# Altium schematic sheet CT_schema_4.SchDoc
size 578 x 363 mm
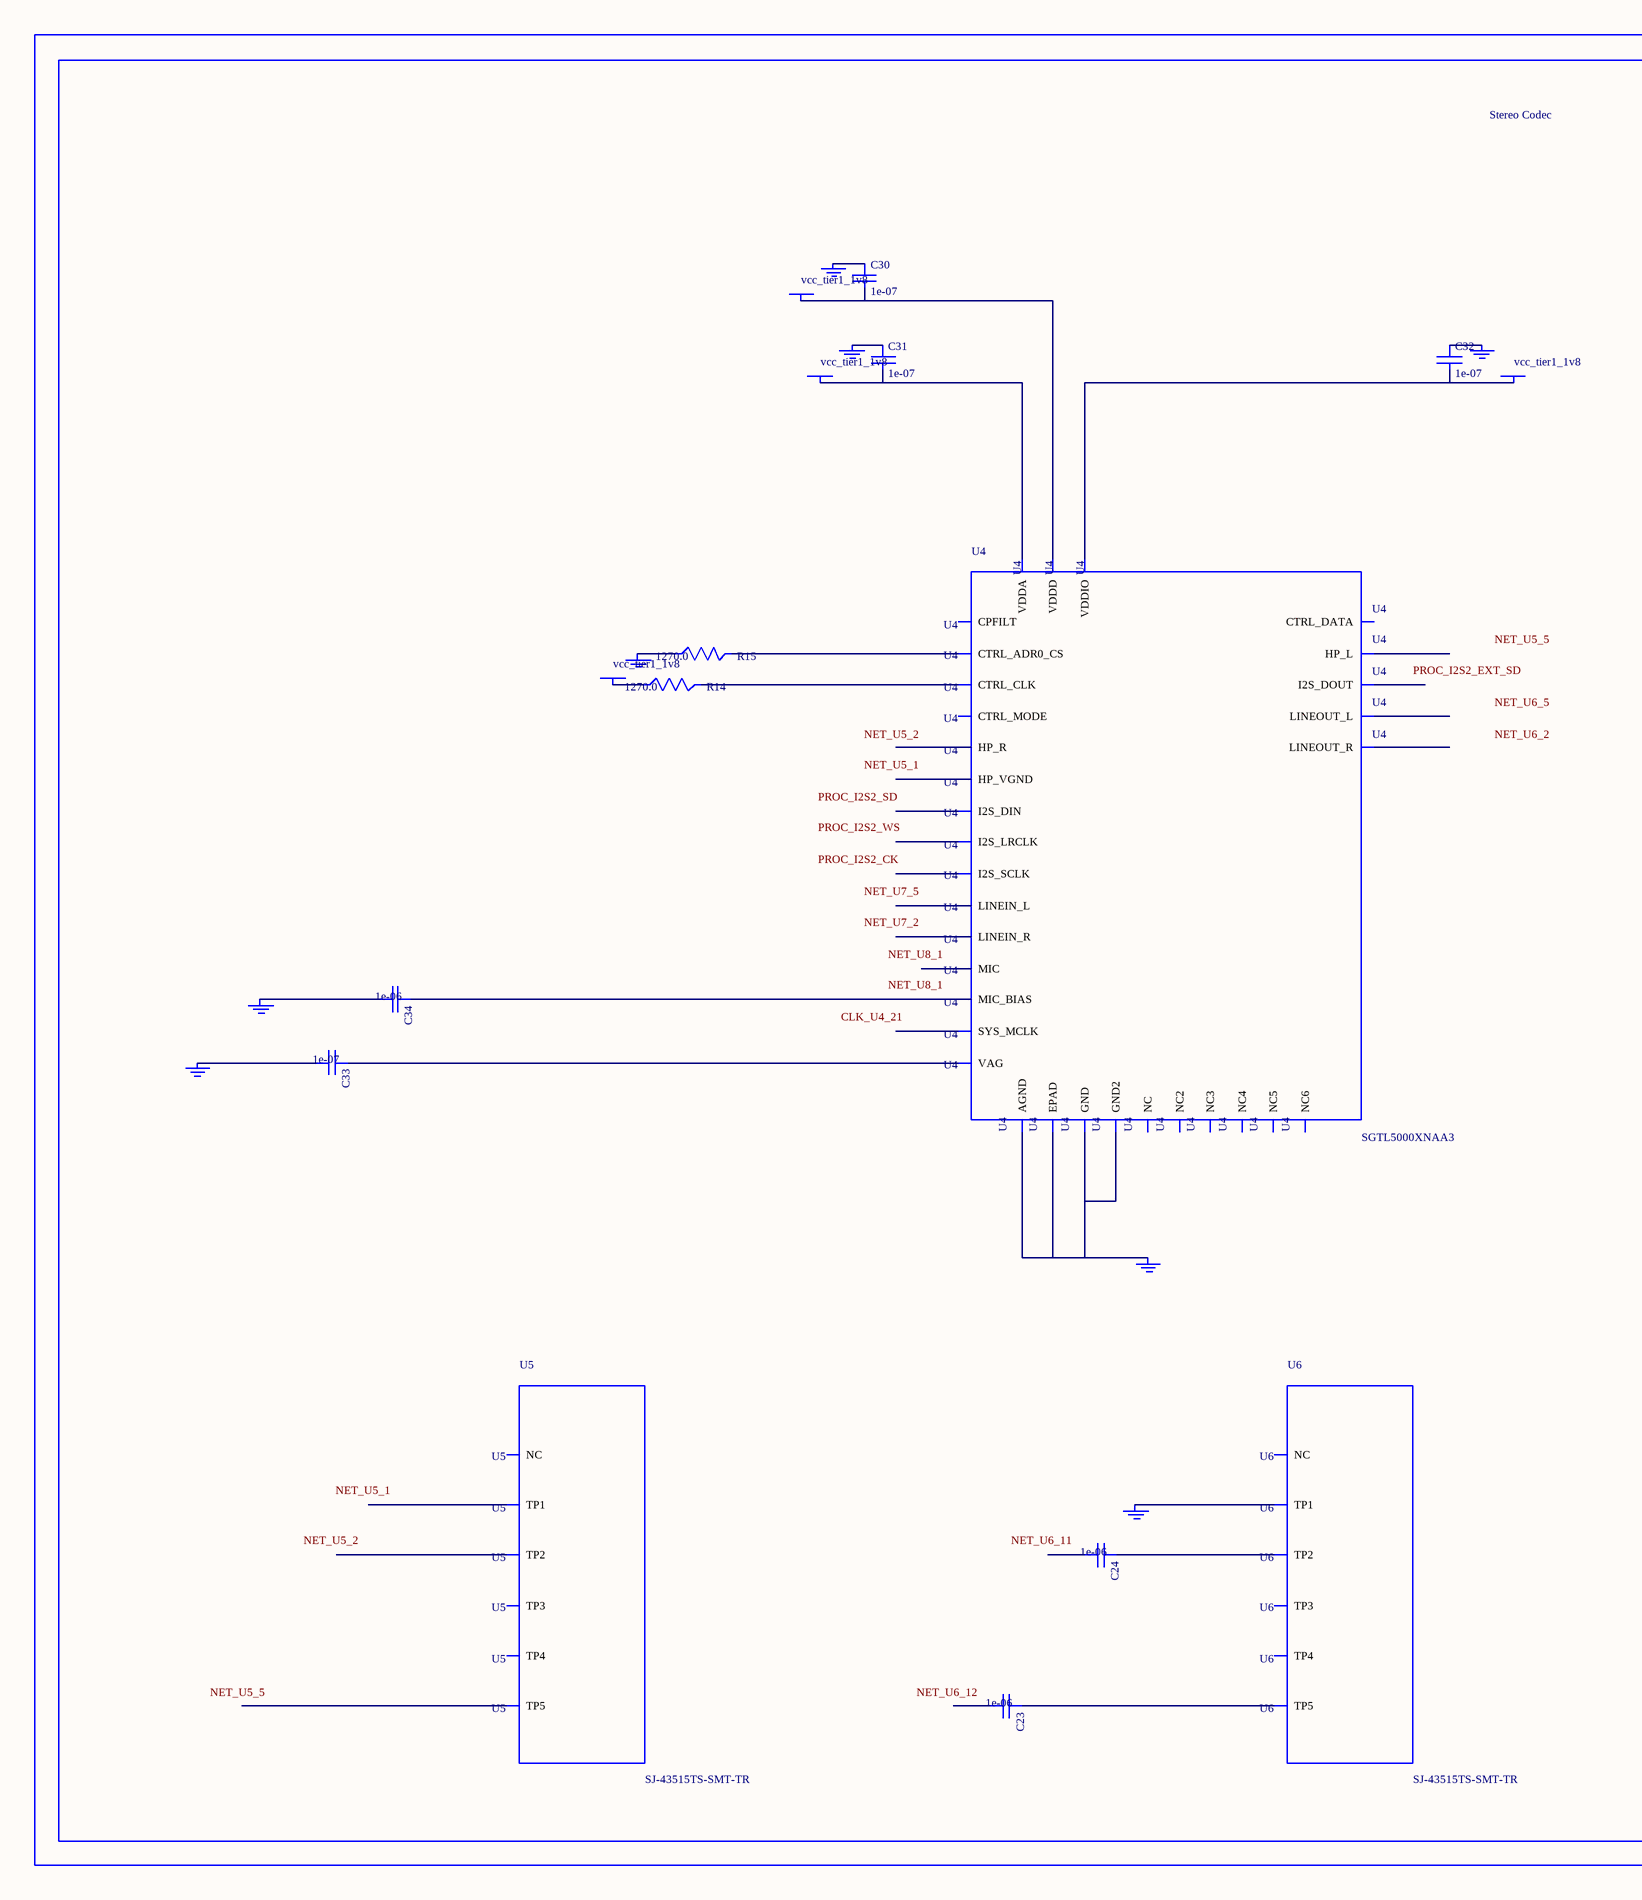
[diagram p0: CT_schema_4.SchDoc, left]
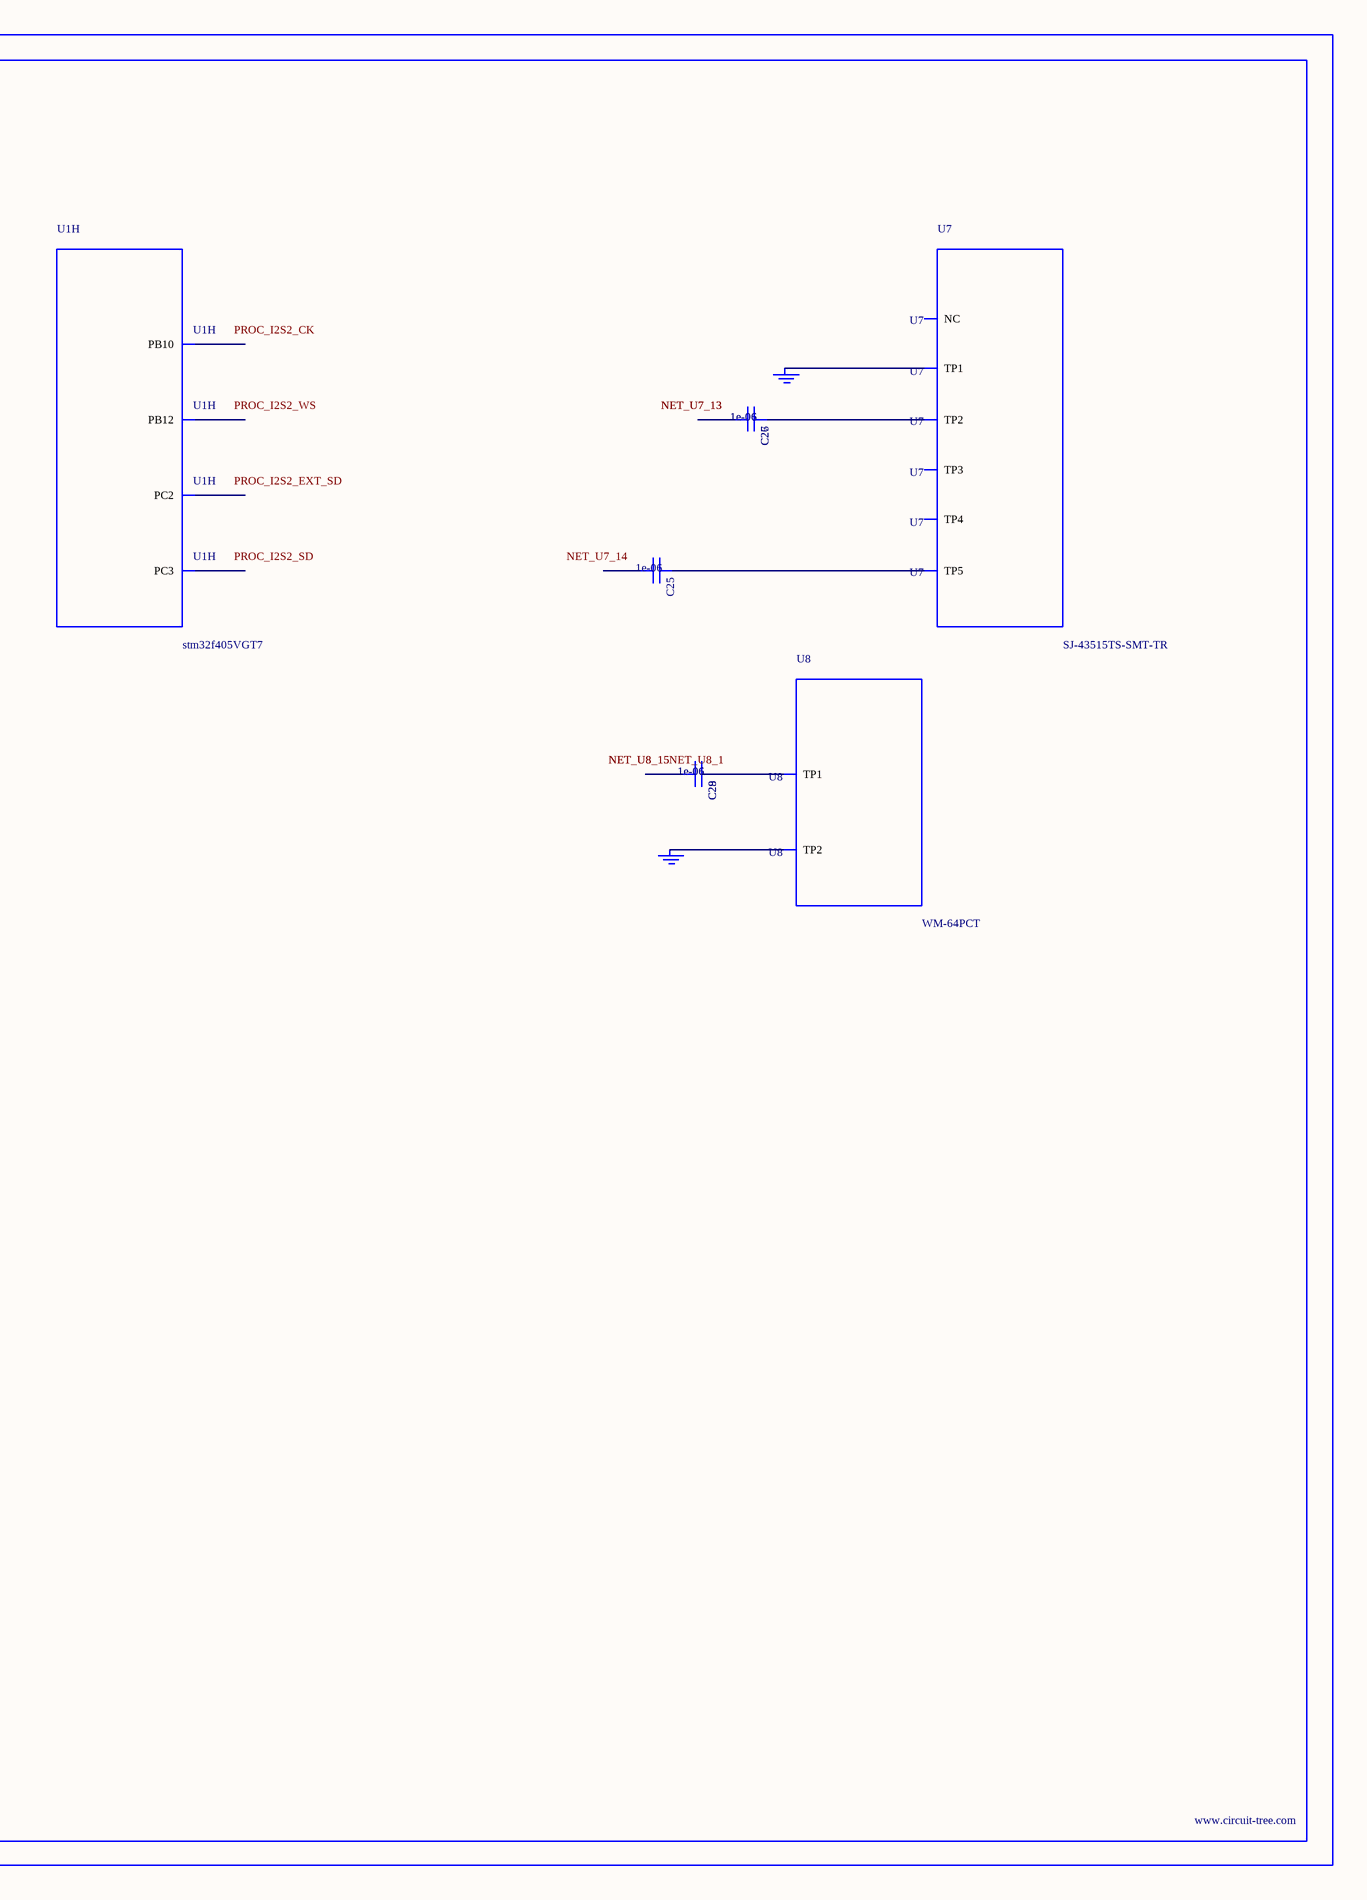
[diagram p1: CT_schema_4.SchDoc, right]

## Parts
BORDER3  (no value)
C23  1e-06  [C0603]
C24  1e-06  [C0603]
C25  1e-06  [C0603]
C26  1e-06  [C0603]
C27  1e-06  [C0603]
C28  1e-06  [C0603]
C29  1e-06  [C0603]
C30  1e-07  [C0402]
C31  1e-07  [C0402]
C32  1e-07  [C0402]
C33  1e-07  [C0402]
C34  1e-06  [C0603]
GND_INSTANCE_3_0  (no value)
GND_INSTANCE_3_1  (no value)
GND_INSTANCE_3_2  (no value)
GND_INSTANCE_3_3  (no value)
GND_INSTANCE_3_4  (no value)
GND_INSTANCE_3_5  (no value)
GND_INSTANCE_3_6  (no value)
GND_INSTANCE_3_7  (no value)
GND_INSTANCE_3_8  (no value)
GND_INSTANCE_3_9  (no value)
GND_INSTANCE_3_10  (no value)
POWER_INSTANCE_3_0  vcc_tier1_1v8
POWER_INSTANCE_3_1  vcc_tier1_1v8
POWER_INSTANCE_3_2  vcc_tier1_1v8
POWER_INSTANCE_3_3  vcc_tier1_1v8
R14  1270.0  [R0603]
R15  1270.0  [R0603]
U1  stm32f405VGT7  [LQFP100]  (part H of 10)
U4  SGTL5000XNAA3  [QFN-32]
U5  SJ-43515TS-SMT-TR  [SJ-43515TS-SMT-TR]
U6  SJ-43515TS-SMT-TR  [SJ-43515TS-SMT-TR]
U7  SJ-43515TS-SMT-TR  [SJ-43515TS-SMT-TR]
U8  WM-64PCT  [WM-64PC]

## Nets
NetC23_1: C23.1 U6.5(TP5)
NetC24_1: C24.1 U6.2(TP2)
NetC25_1: C25.1 U7.5(TP5)
NetC26_1: C26.1 C27.1 U7.2(TP2)
NetC26_2: C26.2 C27.2
NetC28_1: C28.1 C29.1 U8.1(TP1)
NetC28_2: C28.2 C29.2
NetC30_1: C30.1 GND_INSTANCE_3_5.0(GND)
NetC30_2: C30.2 POWER_INSTANCE_3_3.0(PWR) U4.30(VDDD)
NetC31_1: C31.1 GND_INSTANCE_3_1.0(GND)
NetC31_2: C31.2 POWER_INSTANCE_3_0.0(PWR) U4.5(VDDA)
NetC32_1: C32.1 GND_INSTANCE_3_4.0(GND)
NetC32_2: C32.2 POWER_INSTANCE_3_1.0(PWR) U4.20(VDDIO)
NetC33_1: C33.1 U4.10(VAG)
NetC33_2: C33.2 GND_INSTANCE_3_2.0(GND)
NetC34_1: C34.1 U4.16(MIC_BIAS)
NetC34_2: C34.2 GND_INSTANCE_3_3.0(GND)
NetGND_INSTANCE_3_0_0: GND_INSTANCE_3_0.0(GND) U4.1(GND) U4.3(GND2) U4.7(AGND) U4.EXP(EPAD)
NetGND_INSTANCE_3_6_0: GND_INSTANCE_3_6.0(GND) R15.1
NetGND_INSTANCE_3_7_0: GND_INSTANCE_3_7.0(GND) U6.1(TP1)
NetGND_INSTANCE_3_8_0: GND_INSTANCE_3_8.0(GND) GND_INSTANCE_3_9.0(GND) U7.1(TP1)
NetGND_INSTANCE_3_10_0: GND_INSTANCE_3_10.0(GND) U8.2(TP2)
NetPOWER_INSTANCE_3_2_0: POWER_INSTANCE_3_2.0(PWR) R14.1
NetR14_2: R14.2 U4.29(CTRL_CLK)
NetR15_2: R15.2 U4.31(CTRL_ADR0_CS)

Not connected (* = marked no-connect by the designer): C23 2; C24 2; C25 2; U1 17(PC2) 18(PC3) 47(PB10) 51(PB12); U4 2(HP_R) 4(HP_VGND) 6(HP_L) 8(NC) 9(NC2) 11(LINEOUT_R) 12(LINEOUT_L) 13(LINEIN_R) 14(LINEIN_L) 15(MIC) 17(NC3) 18(CPFILT) 19(NC4) 21(SYS_MCLK) 22(NC5) 23(I2S_LRCLK) 24(I2S_SCLK) 25(I2S_DOUT) 26(I2S_DIN) 27(CTRL_DATA) 28(NC6) 32(CTRL_MODE); U5 1(TP1) 2(TP2) 3(TP3) 4(TP4) 5(TP5) 6(NC); U6 3(TP3) 4(TP4) 6(NC); U7 3(TP3) 4(TP4) 6(NC)

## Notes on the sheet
- Labels drawn without touching a wire or pin: CLK_U4_21, NET_U5_1, NET_U5_2, NET_U5_5, NET_U6_2, NET_U6_5, NET_U6_11, NET_U6_12, NET_U7_2, NET_U7_5, NET_U7_14, NET_U8_1, PROC_I2S2_CK, PROC_I2S2_EXT_SD, PROC_I2S2_SD, PROC_I2S2_WS

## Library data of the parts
BORDER3 = BORDER_PAGE3
C23-C29 C34 = C0603C105K3RACTU
C30-C33 = C0402C104K3RACTU
GND_INSTANCE_3_0-GND_INSTANCE_3_10 = GND
POWER_INSTANCE_3_0-POWER_INSTANCE_3_3 = PWR
R14 R15 = RC0603FR-071K27L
